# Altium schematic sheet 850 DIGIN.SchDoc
size Letter; Organization: Toradex Solutions Inc.; Address1: 6415 Northwest Drive; Address2: Mississauga, ON, L4V 1X1; Address3: Canada
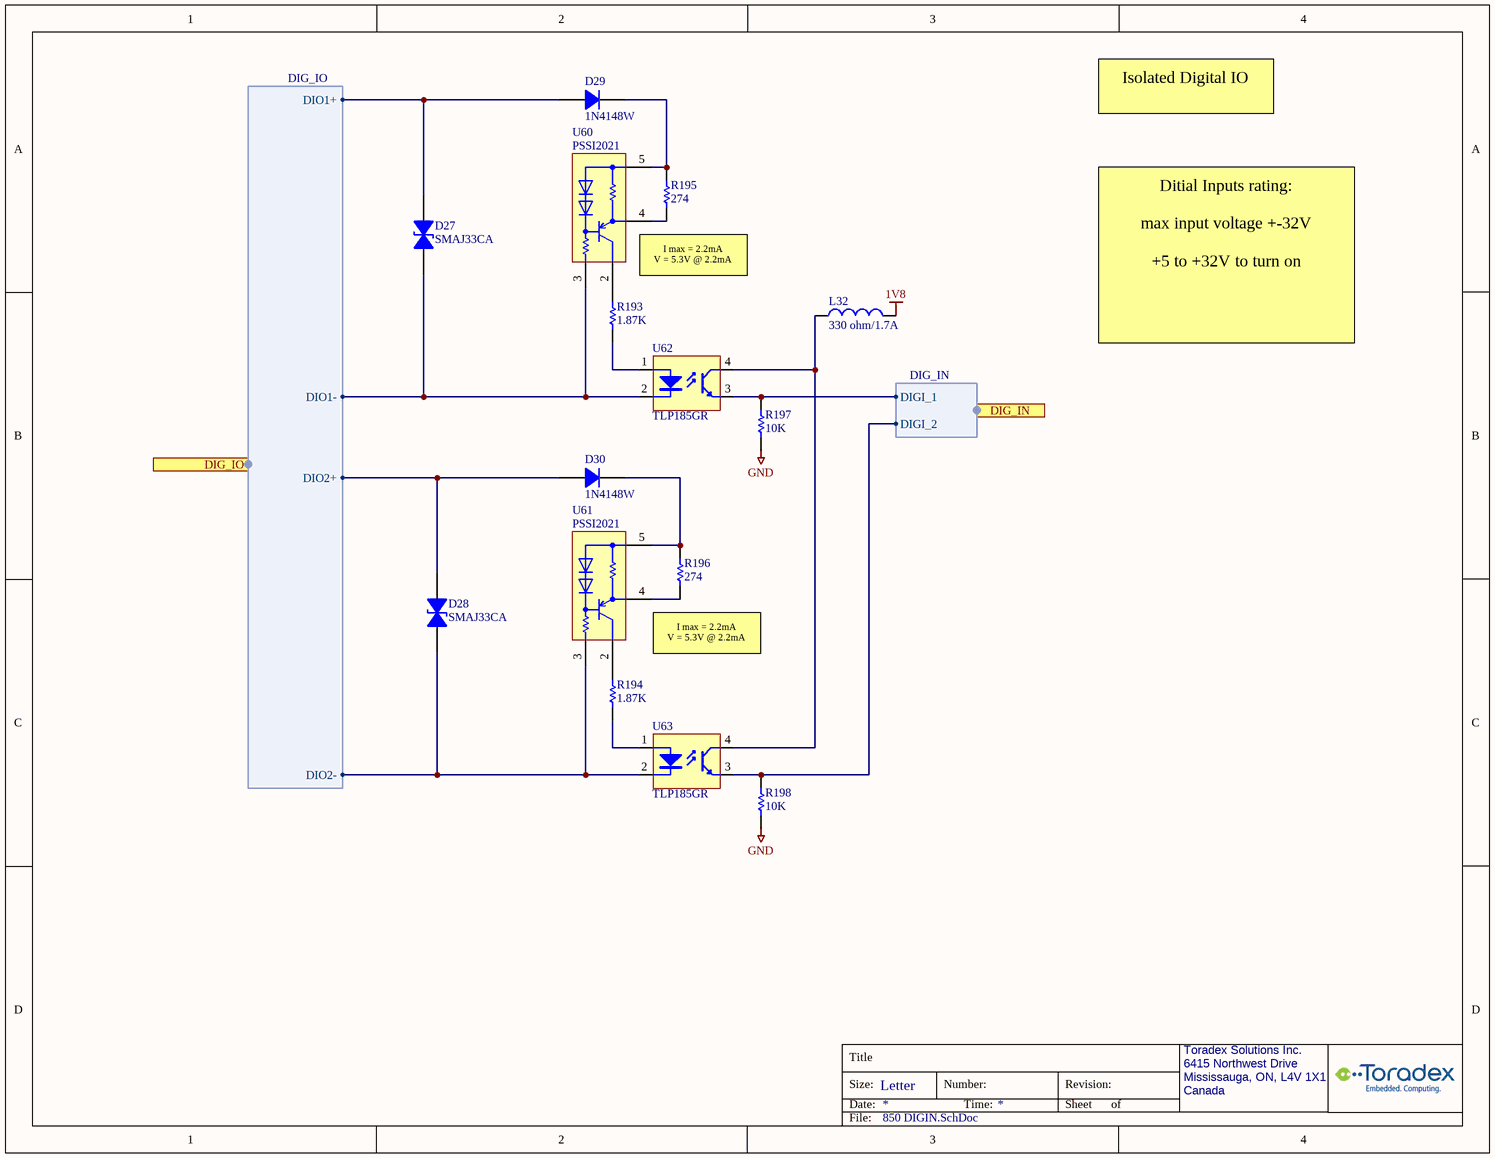
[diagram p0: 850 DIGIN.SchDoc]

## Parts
D27  SMAJ33CA  [SMAJ_TRANSIL]
D28  SMAJ33CA  [SMAJ_TRANSIL]
D29  1N4148W  [SOD123_ALT]
D30  1N4148W  [SOD123_ALT]
L32  value 330 ohm/1.7A  [INDC1608x095]  (hidden comment: 0405-Fer-0603-330ohm/1.7A)
R193  value 1.87K  [R0402_RESC1005L]  (hidden comment: 1536-Res-0402-1.87K)
R194  value 1.87K  [R0402_RESC1005L]  (hidden comment: 1536-Res-0402-1.87K)
R195  value 274  [R/0603]  (hidden comment: 0728-Res-0603-274ohm)
R196  value 274  [R/0603]  (hidden comment: 0728-Res-0603-274ohm)
R197  value 10K  [R0402_RESC1005L]  (hidden comment: 1572-Res-0402-10K)
R198  value 10K  [R0402_RESC1005L]  (hidden comment: 1572-Res-0402-10K)
U60  PSSI2021  [SOT353-5N]
U61  PSSI2021  [SOT353-5N]
U62  TLP185GR  [SOP254P700X210-4N]
U63  TLP185GR  [SOP254P700X210-4N]

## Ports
DIG_IN (harness DIG_IN), DIG_IO (harness DIG_IO)

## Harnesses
DIG_IN: DIGI_1, DIGI_2
DIG_IO: DIO1+, DIO1-, DIO2+, DIO2-

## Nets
1V8: L32.2
GND: R197.1 R198.1
NetD27_1: D27.1 U60.3(Gnd) U62.2(K) ; port DIG_IO.DIO1-
NetD27_2: D27.2 D29.1(A) ; port DIG_IO.DIO1+
NetD28_1: D28.1 U61.3(Gnd) U63.2(K) ; port DIG_IO.DIO2-
NetD28_2: D28.2 D30.1(A) ; port DIG_IO.DIO2+
NetD29_3: D29.3(K) R195.2 U60.5(Vs)
NetD30_3: D30.3(K) R196.2 U61.5(Vs)
NetL32_1: L32.1 U62.4(C) U63.4(C)
NetR193_1: R193.1 U62.1(A)
NetR193_2: R193.2 U60.2(Out)
NetR194_1: R194.1 U63.1(A)
NetR194_2: R194.2 U61.2(Out)
NetR195_1: R195.1 U60.4(Rext)
NetR196_1: R196.1 U61.4(Rext)
NetR197_2: R197.2 U62.3(E) ; port DIG_IN.DIGI_1
NetR198_2: R198.2 U63.3(E) ; port DIG_IN.DIGI_2

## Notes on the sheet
- Isolated Digital IO
- (near U60) I max = 2.2mA
  V = 5.3V @ 2.2mA
- Ditial Inputs rating:
  max input voltage +-32V
  +5 to +32V to turn on
- I max = 2.2mA
  V = 5.3V @ 2.2mA

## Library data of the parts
D27 D28 = 0581-SMAJ33CA: (-55 to 150 DegC) TVS DIODE 33VWM Vbrm:36.7V Vcl:53.3V 400W SMA; MfrNo: SMAJ33CA-E3/5A; Mfr: Vishay Semiconductor Diodes Division; PN: 581; Desc: (-55 to 150 DegC) TVS DIODE 33VWM Vbrm:36.7V Vstd:53.3VC SMA; Alt: SMAJ33CA-E3/61GICT-ND; Alt2: SMAJ33CABCT-ND; DR: SMAJ33CA-E3/5AGIDKR-ND; DR2: 625-SMAJ33CA-E3/5A
D29 D30 = 1159-1N4148W: (-55 to 150 DegC) DIODE GEN PURP 100V 300MA SOD123; MfrNo: 1N4148W-7-F; Mfr: Diodes; PN: 1159; Alt: 1N4148WQ-7-F
L32 = 0405-Fer-0603-330ohm/1.7A: (-55 to 125 DegC) FERRITE BEAD 330 OHM 0603 1.7A 80mohm, typ 48mohm; Mfr: TDK Corporation; MfrNo: MPZ1608S331ATA00; PN: 405; TR: 445-5221-2-ND; DR: 445-5221-6-ND; DR2: 810-MPZ1608S331ATA00
R193 R194 = 1536-Res-0402-1.87K: (-55 to 155 DegC AEC) RES 1.87K OHM 1% 1/16W 100ppm 0402; MfrNo: RMCF0402FT1K87; Mfr: Stackpole Electronics; Alt: AC0402FR-071K87L,RK73H1ETTP1871F,ERJ-2RKF1871X; PN: 1536
R195 R196 = 0728-Res-0603-274ohm: RES SMD 274 OHM 1% 1/10W 0603; MfrNo: RC0603FR-07274RL; Mfr: Yageo; PN: 728; TR: 311-274HRTR-ND
R197 R198 = 1572-Res-0402-10K: (-55 to 155 DegC AEC) RES 10K OHM 1% 1/16W 100ppm 0402; MfrNo: RMCF0402FT10K0; Mfr: Stackpole Electronics; PN: 1572; Alt: AC0402FR-0710KL,AC0402FR-1310KL,CRGCQ0402F10K
U60 U61 = 0394-PSSI2021: (-65 to 150 DegC AEC)  IC CURRENT SOURCE SOT353 75V 50uA-50mA; MfrNo: PSSI2021SAY,115; Mfr: Nexperia USA Inc.; PN: 394
U62 U63 = 1170-Opto-TLP185GR: OPTOISO 3.75KV TRANS 6-SO 4 LEAD TR:100-300%@5mA, 80V, 3.7x7mm; MfrNo: TLP185(GR-TPL,SE; Mfr: Toshiba; PN: 1170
